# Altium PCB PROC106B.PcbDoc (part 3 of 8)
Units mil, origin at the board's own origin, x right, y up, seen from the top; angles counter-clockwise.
Board outline 4498.18 x 1060.53 mil, 8 copper layers (Top Layer, GND1, Sig1, PWR1, PWR2, Sig2, GND2, Bottom Layer), stack 69.602 mil thick; 439 components, 327 nets, 1548 pads, 843 vias.
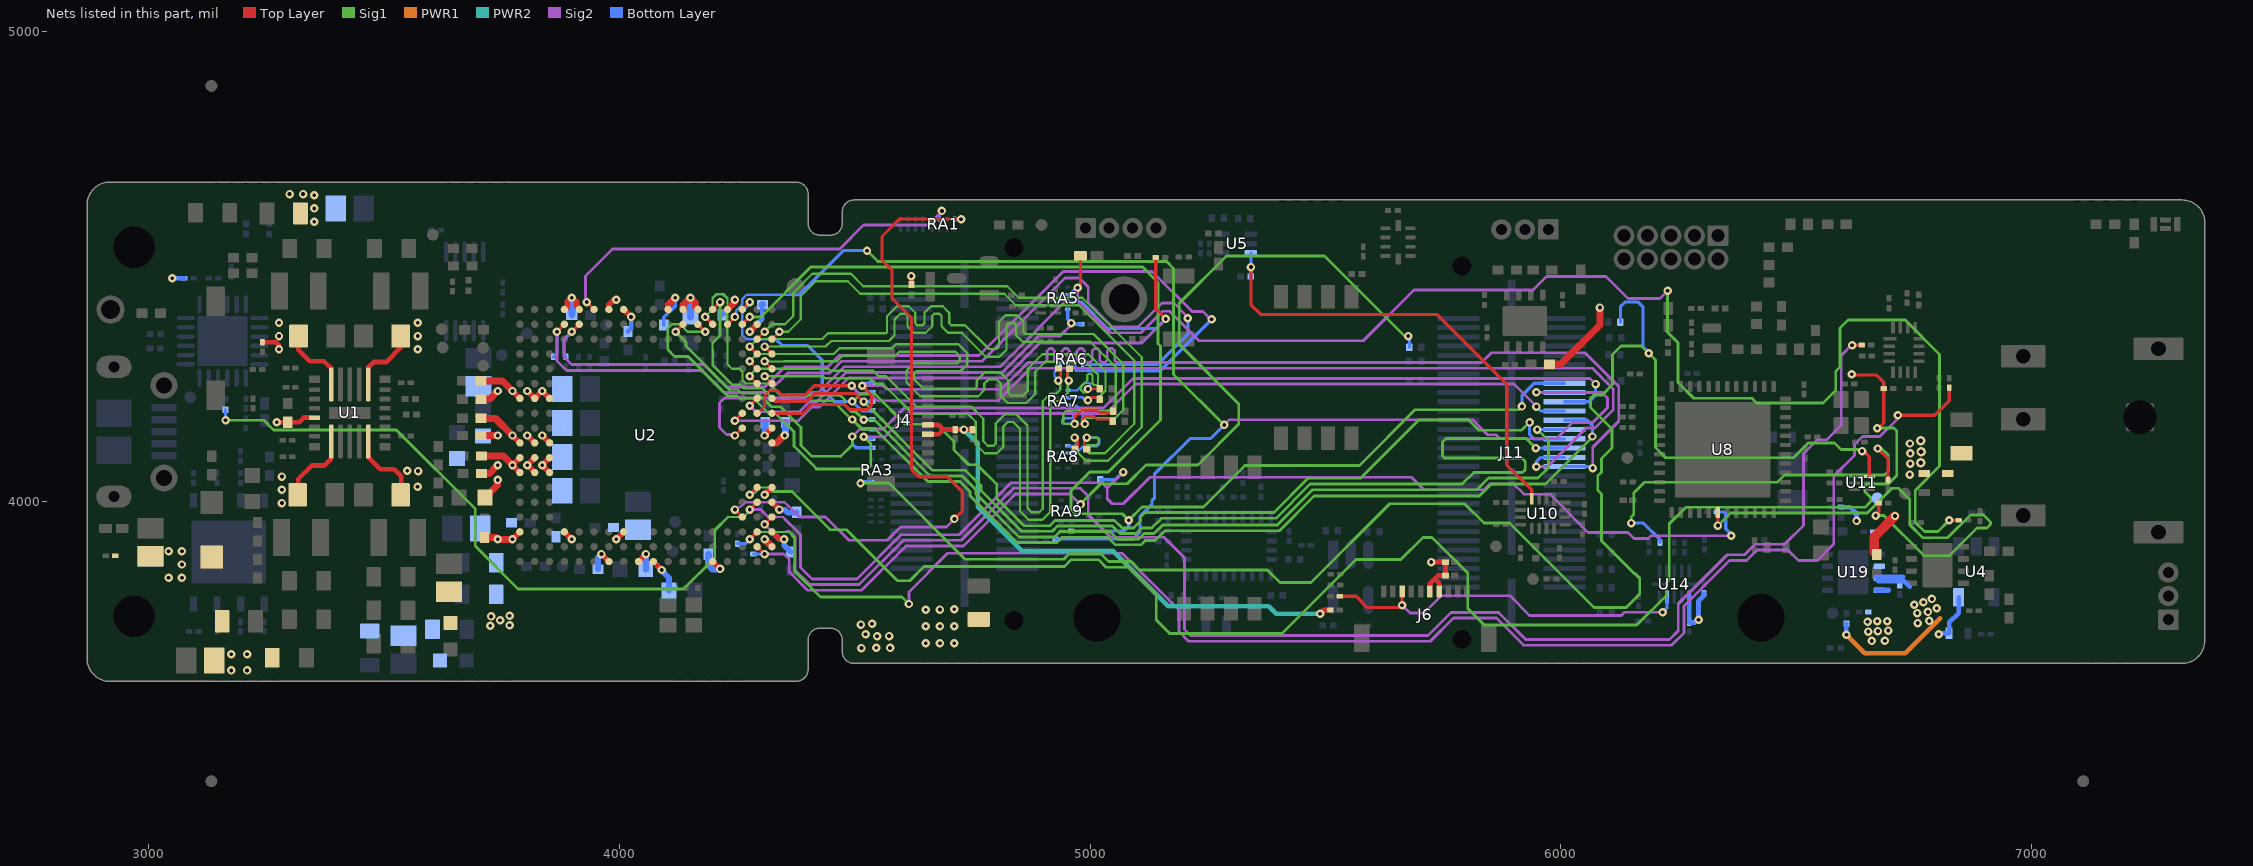
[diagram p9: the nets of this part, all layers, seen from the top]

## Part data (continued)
R52: library part CMP-0090496-1, "Res Thick Film 0201 1.96K Ohm 1% 1/20W 200ppm/C Molded SMD T/R", Digikey Part Number=P122807CT-ND, Manufacturer=Panasonic, Mouser Part Number=667-ERJ-1GNF1961C, Operating Temperature Range="-55°C to +125°C", Power_W=50mW, TempCo=200ppm/°C, Tolerance_%=1%
R53 R54 R55 R56: library part CMP-0026363-2, "RES, 3.83, 1%, 0.063 W, AEC-Q200 Grade 0, 0402", Manufacturer=Vishay-Dale, Power_W=63mW, Supplier Part Number 1=541-3.83LLCT-ND, TempCo="100 ppm/C", Tolerance_%=1%, Value2=0.063W, Value_Code=3R83, ValueDisplayed=3.83
R79 R180 R181: library part CMP-0087184-1, "RESISTOR, 0201, 0.05W, 1%, 4K7", Manufacturer="Panasonic Electronic Components", Power_W=50mW, TempCo=200ppm/°C, Tolerance_%=1%
R114 R117 R119 R126: library part CMP-0026491-2, "RES, 61.9, 1%, 0.063 W, AEC-Q200 Grade 0, 0402", Manufacturer=Vishay-Dale, Power_W=63mW, Supplier Part Number 1=541-61.9LCT-ND, TempCo="100 ppm/C", Tolerance_%=1%, Value2=0.063W, Value_Code=61R9, ValueDisplayed=61.9
R158 R170 R172: library part CMP-0090499-1, "Res Thick Film 0201 82.5K Ohm 1% 1/20W ±200ppm/°C Molded SMD SMD T/R", Digikey Part Number=P123175CT-ND, Manufacturer=Panasonic, Mouser Part Number=667-ERJ-1GNF8252C, Operating Temperature Range="-55°C to +125°C", Power_W=50mW, TempCo=200ppm/°C, Tolerance_%=1%
R159 R171: library part CMP-0090503-1, "Res Thick Film 0201 750 Ohm 5% 0.05W(1/20W) ±200ppm/C Pad SMD Automotive T/R", Digikey Part Number=P123367CT-ND, Manufacturer="Panasonic Electronic Components", Mouser Part Number=667-ERJ-1GNJ751C, Operating Temperature Range="-55°C to +125°C", Power_W=50mW, TempCo=200ppm/°C, Tolerance_%=5%
R174 R176: library part CMP-0090498-1, "Res Thick Film 0201 7.87K Ohm 1% 1/20W ±200ppm/°C Molded SMD SMD T/R", Digikey Part Number=P123160CT-ND, Manufacturer=Panasonic, Mouser Part Number=667-ERJ-1GNF7871C, Operating Temperature Range="-55°C to +125°C", Power_W=50mW, TempCo=200ppm/°C, Tolerance_%=1%
RA1 RA2 RA3 RA4 RA5 RA6 RA7 RA8 RA9: library part CMP-0087186-1, "RES ARRAY 4 RES ZERO OHM 0502", Manufacturer="Panasonic Electronic Components", Power_W=100mW, TempCo=-200/+600ppm/°C, Tolerance_%=5%
S1 S2: library part CMP-0002128-2, "Switch, Slide, SPST 4 poles, SMT", CurrentRating_mA=25A, Manufacturer="CTS Electrocomponents", Supplier Part Number 1=CT2184LPST-ND
S3: library part CMP-0087181-1, "SWITCH SLIDE DIP SPST 100MA 6V", Manufacturer="Nidec Copal Electronics"
SW2 SW3: library part CMP-0002150-2, "SWITCH TACTILE SPST-NO 0.05A 12V", CurrentRating_mA=50A, Manufacturer="Omron Electronic Components", Supplier Part Number 1=SW1020CT-ND
TP2 TP3 TP4 TP5 TP6 TP7 TP8 TP9 TP10 TP12 TP13 TP14 TP15 TP16 TP17 TP18 TP19 TP26 TP27 TP46: library part CMP-0078143-3, "TEST POINT.  No entry in BOM.", Manufacturer=N/A
TP11: library part CMP-0003825-1, "1mm Test Point, SMT", Manufacturer=Any
TP20: library part CMP-0086474-1, "PC Test Point, Loop Brass, Tin Plating 0.047\" (1.19mm) Hole Diameter Mounting Type", Manufacturer="Keystone Electronics"
U1: library part CMP-0079120-2, "4-A + 2.5-A + Two 1.5-A Buck Converters With Integrated Switches, RNF0026C (VQFN-HR-26)", Alternate Manufacturer="Texas Instruments", Alternate PartNumber=LP87524JRNFTQ1
U2: library part CMP-0090288-2, Manufacturer="Texas Instruments", Operating Temperature Range=to
U3: library part CMP-0087172-1, "I/O Controller Interface IC USB to Dual UART bridge", Manufacturer="Silicon Labs"
U4: library part CMP-0035419-1, "Single Output High PSRR LDO, 200 mA, Fixed 3 V Output, 2.7 to 5.5 V Input, 5-pin SOT-23 (DBV), -40 to 85 degC, Green (RoHS & no Sb/Br)", Manufacturer="Texas Instruments", Rating=Catalog
U5: library part CMP-0067398-2, "Automotive Grade, 1.4V-Capable +/-0.5degC Temperature Sensor with Alert Function and I2C/SMBus, DRL0006A (SOT-OTHER-6)", Alternate Manufacturer="Texas Instruments"
U6: library part CMP-0087170-1, "8KB I2C SER EEPROM TSOT 23", Manufacturer="ON Semiconductor"
U7: library part CMP-0087171-1, "IMU ACCEL/GYRO/MAG I2C 32BIT", Manufacturer="Hillcrest Laboratories, Inc."
U8: library part CMP-0083675-2, "SimpleLink(TM) Bluetooth(R) 5 low energy Wireless MCU, RGZ0048A (VQFN-48)", Alternate Manufacturer="Texas Instruments", Alternate PartNumber=CC2642R1FRGZT, Operating Temperature Range="-40 to 85 C", Rating=#N/A
U9: library part CMP-0079267-1, "2.3V-3.6V, 16M-BIT [x 1/x 2/x 4] CMOS FLASH Memory, WSON-8", Manufacturer="Macronix International Co., LTD", Supplier Part Number 1=1092-1211-ND
U10: library part CMP-0043349-1, "Low-Voltage 8-Bit I2C and SMBus I/O Expander, 1.65 to 5.5 V, -40 to 85 degC, 16-pin UQFN (RSV), Green (RoHS & no Sb/Br)", 5V Tolerant I/O=Yes, Manufacturer="Texas Instruments", Max Frequency(kHz)=400
U11: library part CMP-0050992-5, "1-Channel, 2:1 Analog Switch, DSF0006A (X2SON-6)", F @ Nom Voltage(Max)(Mhz)=150, Generic Part Number=SN74LVC1G3157, ICC @ Nom Voltage(Max)(mA)=0.01, Manufacturer="Texas Instruments", Operating Temperature Range="-40 to 85 C", Rating=Catalog, tpd @ Nom Voltage(Max)(ns)=2,1.2,0.8,0.3, Voltage(Nom)(V)=1.8,2.5,3.3,5
U12 U17: library part CMP-0065183-3, "Automotive Fault Protected CAN Transceiver With Flexible Data-Rate, DRB0008F (VSON-8)", Alternate Manufacturer="Texas Instruments", Alternate PartNumber=TCAN1042HGVDRBTQ1, Operating Temperature Range="-55 to 125 C", Rating=Automotive
U13: library part CMP-0067415-1, "10-Ohm Quad SPDT Analog Switch, RSV0016A (UQFN-16)", Alternate Manufacturer="Texas Instruments"
U14: library part CMP-0860038-1, "Automotive 4-Bit Bidirectional Voltage-Level Translator with Auto Direction Sensing and +/-15kV ESD, RUT0012A (UQFN-12)", Alternate Manufacturer="Texas Instruments", Operating Temperature Range="-40 to 125 C", Rating=Automotive
U15: library part CMP-0074545-1, "Dual 10-ohm SPDT Analog Switch, RSE0010A (UQFN-10)", Alternate Manufacturer="Texas Instruments"
U16: library part CMP-0087998-2, "AND Gate IC 1 Channel  6-SON (1x1)", Digikey Part Number=296-30121-1-ND, Manufacturer="Texas Instruments", Max Supply Voltage=5.5V, Min Supply Voltage=1.65V, Mouser Part Number=595-SN74LVC1G11DSFR, Operating Temperature Range="-40°C to +125°C"
U18: library part CMP-0074341-1, "Automotive Catalog Dual 15-Ohm SPDT Analog Switch, DGS0010A (VSSOP-10)", Alternate Manufacturer="Texas Instruments"
U19: library part CMP-0043358-3, "Dual In / Single Out Autoswitching Power Mux, 2.8 to 5.5 V, -40 to 85 degC, 8-pin SON (DRB), Green (RoHS & no Sb/Br)", IN1, IN2 Input Voltage(Max)(V)=5.5, IN1, IN2 Input Voltage(Min)(V)=2.8, IN1 Output Current(Max)(A)=1.25, Manufacturer="Texas Instruments"
Y1: library part CMP-0090505-1, "40MHz ±10ppm Crystal 8pF 50 Ohms 4-SMD, No Lead", Digikey Part Number=FW4000044QDICT-ND, Frequency_Fixed=40MHz, Frequency Stability=50ppm, Frequency Tolerance=10ppm, Load Capacitance=8pF, Manufacturer=Diodes, Mouser Part Number=729-FW4000044Q, Operating Temperature Range="-40°C to +125°C"
Y2: library part CMP-0088076-1, "48MHz ±20ppm Crystal 7pF 50 Ohms 4-SMD, No Lead", Frequency_Fixed=48MHz, Frequency Tolerance=20ppm, Load Capacitance=7pF, Manufacturer=Kyocera
Y3 Y4: library part CMP-0088006-1, "CRYSTAL 32.768KHZ 4PF SMD", Frequency_Fixed=32.768kHz, Frequency Tolerance=20ppm, Load Capacitance=4pF, Manufacturer="Abracon LLC"
ZZ1: library part CMP-0003616-3
ZZ2: library part CMP-0077236-1
ZZ3: library part CMP-0077237-1
ZZ4 ZZ5.2: library part CMP-0077238-1
ZZ5.1: library part CMP-0077238-1, "Cut the thermal pad(Part Number#GPVOUS-0.125-AC-0816) for the shape and size of the inner surface of the heatsink(Part Number#160018120021) and paste it on the inner surface of the heatsink;"

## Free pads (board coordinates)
  round 19 hole 24 unplated: ""(3145.41,4687.43) ""(3145.41,3610.9) ""(3175.41,4687.43) ""(3175.41,3610.9) ""(3205.41,4687.43) ""(3205.41,3610.9) ""(3235.41,4687.43) ""(3235.41,3610.9) ""(3265.41,4687.43) ""(3265.41,3610.9) ""(3637.19,4687.43) ""(3637.19,3610.9) ""(3667.19,4687.43) ""(3667.19,3610.9) ""(3697.19,4687.43) ""(3697.19,3610.9) ""(3727.19,4687.43) ""(3727.19,3610.9) ""(3757.19,4687.43) ""(3757.19,3610.9) ""(4128.97,3610.9) ""(4128.97,4687.43) ""(4158.97,3610.9) ""(4158.97,4687.43) ""(4188.97,4687.43) ""(4188.97,3610.9) ""(4218.97,3610.9) ""(4218.97,4687.43) ""(4248.97,3610.9) ""(4248.97,4687.43) ""(4646.5,3648.05) ""(4676.5,3648.05) ""(4706.5,3648.05) ""(4736.5,3648.05) ""(4766.5,3648.05) ""(5409.11,4649.48) ""(5439.11,4649.48) ""(5469.11,4649.48) ""(5499.11,4649.48) ""(5529.11,4649.48) ""(5950.52,3648.05) ""(5980.52,3648.05) ""(6010.52,3648.05) ""(6040.52,3648.05) ""(6070.52,3648.05) ""(7097.6,3648.05) ""(7097.68,4649.43) ""(7127.6,3648.05) ""(7127.68,4649.43) ""(7157.6,3648.05) ""(7157.68,4649.43) ""(7187.6,3648.05) ""(7187.68,4649.43) ""(7217.6,3648.05) ""(7217.68,4649.43)

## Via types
v1: diameter 18, hole 8, Top Layer to Bottom Layer, tented both sides, 804 vias
v2: diameter 19.68, hole 7.87, Top Layer to Bottom Layer, tented both sides, 34 vias
v3: diameter 20, hole 10, Top Layer to Bottom Layer, tented both sides, 3 vias
v4: diameter 18, hole 8, Top Layer to Bottom Layer, 1 vias
v5: diameter 17, hole 7.87, Top Layer to Bottom Layer, 1 vias

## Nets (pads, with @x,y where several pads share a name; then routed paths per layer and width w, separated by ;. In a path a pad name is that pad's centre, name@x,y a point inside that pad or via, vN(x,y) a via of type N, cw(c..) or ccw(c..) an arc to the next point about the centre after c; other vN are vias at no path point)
3V0: C7.1 C15.1 C16.1 C115.1 C116.1 C118.1 J4.6 J4.7 J6.6 J6.7 R79.2 R181.2 U4.5 U14.1 | length 1553.4
  Top Layer w10: J4.7@4655.33,4143.81 4678.32,4143.81 4688.3,4153.79 ; J4.6@4655.33,4163.49 4678.59,4163.49 4688.3,4153.79 ; C15.1@4750.21,4153.69 4750.12,4153.79 v1(4731.8,4153.79) C16.1@4713.47,4153.79 4688.3,4153.79 ; v1(5488.42,3762.4) 5496.67,3770.65 R181.2@5510.03,3770.65 ; J6.6@5721.75,3810.06 5721.75,3826.54 5731.98,3836.77 ; v1@5724.8,3872.26 5724.87,3872.2 C115.1@5754.85,3872.2 C116.1@5754.85,3843.74 5738.95,3843.74 5731.98,3836.77 ; J6.7@5741.43,3807.06 5741.43,3827.32 5731.98,3836.77
  PWR2 w10: v1(4731.8,4153.79) 4761,4124.58 4761,3989.4 4854.25,3896.15 5048.17,3896.15 5165.74,3778.57 5379.01,3778.57 5395.18,3762.4 v1(5488.42,3762.4)
  Bottom Layer w10: U14.1@6272.54,3799.77 6272.54,3764.35 6272.5,3764.32 C118.1@6272.5,3743.88 6284.34,3743.88 6292.44,3751.98 6292.44,3789.79 6304.11,3801.46 R79.2@6304.11,3805.64 ; v1(6802.79,3718.79) 6804.79,3720.79 C7.1@6824.78,3720.79 6824.78,3743.97 6844.78,3763.97 U4.5@6844.78,3797.49
  other v1: 6292.44,3749.79 5724.6,3872.26
5V_HD_IN: C128.1 L16.2 R20.1 U19.8 | length 78.8
  Bottom Layer w10: R20.1@6594.7,3988.94 6614.05,3988.94 6628.05,3974.95 v1(6628.05,3959.58)
  Bottom Layer w12: U19.8@6671.07,3812.08 6695.37,3812.08
  other v1: 4650.94,3699.61 4681.04,3699.61 4711.61,3699.61 6660.22,3704.68 6688.14,3705.36 6652.66,3724.54 6673.29,3725.69 6695.37,3726.86 4650.94,3735.76 4681.04,3735.76 4711.61,3735.76 6651.3,3745.4 6671.76,3746.63 6693.22,3746.68 4650.93,3770.89 4681.04,3771.4 4711.61,3772.13
5V_IN: C1.2 C4.1 C30.1 C50.1 C51.1 C52.1 C53.1 C129.1 D1.1 FL3.2 FL12.2 R27.1 R39.1 R50.2 R64.1 R107.1 U1.9 U1.13 U1.18 U1.22 U1.26 U19.7 | length 1553.7
  Top Layer w10: R50.2@3241.63,4339.44 3270.32,4339.44 3277.02,4332.74 v1@3277.02,4326.81 ; v1(3272.33,4169.32) C30.1@3295.87,4169.32 3319.81,4169.32 3329.65,4179.16 U1.18@3352.68,4179.16 ; C50.1@3318.11,4009.52 3318.11,4048.7 3346.62,4077.21 3373.07,4077.21 3388.04,4092.18 ; C52.1@3318.11,4368.48 3318.11,4323.58 3342.64,4299.04 3372.63,4299.04 3388.11,4283.56 U1.13@3388.11,4249.63 ; 3388.11,4092.18 U1.22@3388.11,4128.37 ; U1.26@3466.85,4128.37 3466.85,4094.45 3492.01,4069.29 3521.99,4069.29 3536.85,4054.43 C51.1@3536.85,4009.52 ; U1.9@3466.85,4249.63 3466.85,4285.9 3478.07,4297.12 3504.66,4297.12 3536.85,4329.31 C53.1@3536.85,4368.48 ; v1(4620.27,4479.75) 4620.57,4479.46 R107.1@4620.57,4461.7
  Top Layer w15: FL12.2@5975.6,4292.41 5999,4292.41 6082.75,4376.16 v1(6082.75,4412.79)
  Top Layer w20: FL3.2@6670.79,3888.25 6665.81,3893.23 6665.81,3926.17 v5(6709.55,3969.91)
  PWR1 w10: v1(6606.39,3717.68) 6645.55,3678.52 6731.31,3678.52 6805.46,3752.67
  Bottom Layer w10: v1(3050.47,4475.15) R64.1@3076.13,4475.15 ; v1(6606.39,3717.68) R27.1@6606.39,3741.52 ; U19.7@6673.76,3836.69 6698.11,3836.69 6703.21,3831.6 ; 6711.81,3839.4 6710.11,3841.1 ; 6726.91,3841.1 6710.11,3841.1 ; 6740.73,3819.94 6729.08,3831.6 6703.21,3831.6 ; 6703.21,3831.6 6673.82,3831.6 6669.11,3840.2 6670.01,3841.1 6710.11,3841.1
  other v1: 4514.3,3689.55 4545.9,3690.22 4574.96,3689.89 4547.43,3714.8 4572.89,3715.13 4522.96,3718.74 4513.24,3739.55 4536.9,3741.13 6757.93,3742.77 6782.31,3747.33 6756.77,3763.83 6779.56,3766.42 6798.43,3774.05 6750.69,3781.76 6770.14,3787.01 6788.19,3794.02 3042.55,3838.89 3070.75,3838.89 3070.75,3867.09 3042.55,3895.28 3070.75,3895.28 3283.23,3997.47 3283.23,4025.66 3571.45,4032.48 3283.23,4053.86 3549.23,4066.35 3572.38,4065.53 3277.02,4324.15 3571.73,4324.15 3277.02,4352.35 3571.73,4352.35 3277.02,4380.54 3571.73,4380.54
5V_IN_B: C42.2 C122.1 C127.1 L15.2 TP4.1 U19.6
  other v1: 6741.2,4058 6741.81,4081.54 6741.81,4103 6741.32,4124.11
  other v3: 6764.6,4082.97 6765.01,4106.67 6764.46,4130
ALERT: R38.1 U5.3 U10.4 | length 1009.2
  Top Layer w6.7: v1(5341.5,4498.97) 5341.5,4418.98 5362.14,4398.33 5736.3,4398.33 5885.05,4249.58 5885.05,4078.41 5937.93,4025.53 U10.4@5937.93,4006.69
  Bottom Layer w6.7: R38.1@5341.5,4478.82 v1(5341.5,4498.97) U5.3@5341.5,4529.03 U5.3@5341.84,4528.69
AR_1P0_RF1: C75.2 C78.1 C79.1 C80.1 C81.1 C113.1 C124.2 L12.2 U2.J16 U2.J17 U2.J18 | length 184.7
  Top Layer w12: v1(3773.02,4141.13) U2.J18@3788.76,4125.38 ; v1(3804.51,4141.13) U2.J17@3820.26,4125.38 ; v1(3836.01,4141.13) U2.J16@3851.76,4125.38
  Top Layer w15: C80.1@3705.88,4141.13 v1(3741.52,4141.13) ; C81.1@3705.88,4177.66 3736.48,4177.66 v1(3773.02,4141.13)
  other v1: 3725.88,3737.02 3766.78,3737.9 3746.66,3748.61 3727.42,3756.7 3766.78,3758.45
AR_1P0_RF2: C70.1 C74.1 C82.1 C83.1 C84.1 C85.1 C111.2 C121.1 C131.2 L14.2 U2.G16 U2.G17 U2.G18 U2.H16 U2.H17 U2.H18 | length 297.2
  Top Layer w12: U2.G18@3788.76,4062.39 v1(3773.02,4078.14) U2.H18@3788.76,4093.88 ; U2.G17@3820.26,4062.39 v1(3804.51,4078.14) U2.H17@3820.26,4093.88 ; U2.G16@3851.76,4062.39 v1(3836.01,4078.14) U2.H16@3851.76,4093.88
  Top Layer w15: C84.1@3707.42,4060.46 3723.84,4060.46 v1(3741.52,4078.14) ; C85.1@3707.42,4097.51 3753.64,4097.51 v1(3773.02,4078.14) ; C74.1@3714.74,4009.15 3741.52,4035.93 v1(3741.52,4046.64)
AR_1P2: C76.1 C91.2 C92.2 C94.1 C95.1 C96.1 C97.1 C98.1 C103.1 L13.2 U2.A5 U2.C1 U2.E1 U2.J1 U2.V4 U2.V6 U2.V7 U2.V8 U2.V12 U2.V14 U2.V15 | length 667.8
  Top Layer w12: U2.V15@3883.25,4408.84 3890,4415.59 3890,4425.59 3899,4434.59 3909,4424.59 3909,4417 3914.75,4411.25 U2.V14@3914.75,4408.84 ; U2.V12@3977.74,4408.84 3977.74,4418.84 3988.49,4429.59 v1(3993.49,4429.59) ; U2.A5@4198.21,3873.41 v1(4213.96,3857.66) ; U2.C1@4324.2,3936.4 4339.94,3920.65 v1(4349.94,3920.65) ; U2.E1@4324.2,3999.4 4324.33,3999.4 v1(4340.08,3983.65)
  Top Layer w15: U2.V8@4103.72,4408.84 4103.72,4418.45 v1(4118.96,4433.68) ; U2.V7@4135.22,4408.84 4135.22,4417.93 v1(4150.97,4433.68) 4161.76,4422.88 4161.76,4413.8 U2.V6@4166.72,4408.84 ; U2.V4@4229.71,4408.84 4245.46,4424.59 v1(4245.46,4429.68) ; U2.J1@4324.2,4125.38 4334.2,4125.38 v1@4350.05,4141.24
  Bottom Layer w8: C96.1@4094.31,4375.82 4094.31,4392.25 4118.96,4416.91 v1(4118.96,4433.68)
  Bottom Layer w10: v1@3898.96,4434.55 v1@3899,4434.59 ; v1(4150.97,4433.68) v1@4150.97,4434.59
  Bottom Layer w12: C91.2@4218.02,4397.33 4245.46,4424.77 v1(4245.46,4429.68) ; v1(4340.08,3983.65) 4351.45,3983.65 4358.24,3976.86 4375.3,3976.86 C95.1@4376.53,3978.09 ; v1@4350,3920 4350,3908 C94.1@4364,3894
  Bottom Layer w15: C98.1@3898.96,4396.76 v1@3898.96,4434.55 ; C103.1@4150.97,4392.63 v1(4150.97,4433.68) ; C97.1@4188.97,3888.79 4189.39,3888.36 4189.39,3866.45 4198.18,3857.66 v1(4213.96,3857.66) ; v1@4350.05,4141.24 4352.69,4143.87 C92.2@4352.69,4168.77
  other v1: 4351.25,4141.24 3899,4433.68 3352.15,4595.26 3352.15,4623.45 3352.15,4651.65 3299.59,4653.99 3328.09,4653.99
AR_1V4_APLL: C90.1 U2.A10 | length 56.1
  Top Layer w12: U2.A10@4040.73,3873.41 v1(4056.48,3889.16)
  Bottom Layer w10: C90.1@4056.23,3855.43 C90.1@4056.48,3855.68
  Bottom Layer w12: C90.1@4056.48,3855.68 v1(4056.48,3889.16)
AR_1V4_SYNTH: C89.1 U2.A9 | length 72
  Top Layer w12: U2.A9@4072.23,3873.41 v1@4087.98,3857.66
  Bottom Layer w12: v1(4090.2,3855.43) 4090.2,3853.81 4105.41,3838.6 C89.1@4105.41,3811.96
AR_1V8: C55.1 C56.1 C57.1 C58.1 C59.1 C60.1 C61.1 C62.1 C63.1 C64.1 C65.1 C66.1 C67.1 C68.1 C73.2 C112.1 L11.2 U2.A12 U2.B1 U2.C11 U2.C15 U2.C18 U2.F1 U2.K1 U2.M16 U2.M17 U2.M18 U2.U2 U2.V11 | length 635.6
  Top Layer w12: v1(3773.02,3920.65) U2.C18@3788.76,3936.4 ; v1(3773.02,4235.62) U2.M18@3788.76,4219.87 ; v1(3804.51,4235.62) U2.M17@3820.26,4219.87 v1(3836.01,4235.62) U2.M16@3851.76,4219.87 ; U2.C15@3883.25,3936.4 v1(3899,3920.65) ; v1(3961.99,3889.16) U2.A12@3977.74,3873.41 ; v1(3993.49,3920.66) U2.C11@4009.24,3936.4 ; U2.V11@4009.24,4408.84 v1(4024.98,4393.1) ; v1(4276.95,4361.6) U2.U2@4292.7,4377.35 ; v1(4308.45,4015.14) U2.F1@4324.2,4030.89 ; v1(4308.45,4141.13) U2.K1@4324.2,4156.88
  Top Layer w15: C58.1@3705.86,4218.19 3724.1,4218.19 v1(3741.52,4235.62) ; C57.1@3705.86,4257.19 3751.44,4257.19 v1(3773.02,4235.62) ; C68.1@3713.57,3924.11 3738.07,3924.11 v1(3741.52,3920.65) v1(3773.02,3920.65) ; v1(4308.45,3920.65) U2.B1@4324.2,3904.91
  Bottom Layer w10: C61.1@4018.33,4361.9 4024.98,4368.55 v1(4024.98,4393.1) ; v1(4276.95,4361.6) 4303.38,4388.02 C56.1@4303.38,4418.18 ; v1(4308.45,4141.13) v1@4309.75,4142.43
  Bottom Layer w12: C63.1@3954.76,3856.83 3954.76,3881.92 v1(3961.99,3889.16)
  Bottom Layer w15: C56.1@4303.38,4418.18 C56.1@4304.26,4419.07 ; v1@4309.75,4142.43 C60.1@4309.75,4168.77
  other v1: 3175.57,3642.06 3209.12,3642.06 3175.57,3676.64 3209.12,3676.64
AR_BSS_LOGGER: RA1.4 U2.D3 | length 1457.8
  Top Layer w6.7: v1(4245.46,3983.65) U2.D3@4261.2,3967.9 ; v1(4711.71,3963.9) 4728.31,3980.49 4728.31,4021.77 4696.67,4053.41 4635.8,4053.41 4620.6,4068.61 4620.6,4390.98 4579.49,4432.09 4579.49,4491.76 4557.8,4513.46 4557.8,4563.91 4594.61,4600.72 4725.6,4600.72 v1(4725.75,4600.58)
  Sig2 w4.5: v1(4245.46,3983.65) 4250.76,3988.95 4256.7,3988.95 4267.15,3999.4 4350.75,3999.4 4358.91,3991.23
  Sig2 w5.95: 4358.91,3991.23 4382.26,3967.89 4438.09,3967.89 4487.48,3918.5 4569.04,3918.5 4597.24,3946.7 4694.51,3946.7 v1(4711.71,3963.9)
  Bottom Layer w6.7: RA1.4@4711.71,4600.58 v1(4725.75,4600.58)
AR_CS1: R9.2 R139.2 U2.C2 | length 3317
  Top Layer w6.7: v1(4276.95,3920.66) U2.C2@4292.7,3936.4 ; v1(6715.81,4184) 6794.11,4184 6824.81,4214.7 R139.2@6824.81,4242.98
  Sig1 w4.5: v1(4276.95,3920.66) 4292.55,3936.25 ; 4292.57,3936.4 4359.48,3936.4 4367.2,3928.68
  Sig1 w5.95: 4367.2,3928.68 4372.68,3923.2 4372.68,3852.89 4427.56,3798 4600.39,3798 v1(4615.19,3783.2)
  Sig2 w5.95: v1(4615.19,3783.2) 4615.19,3808.93 4697.19,3890.93 5068.04,3890.93 5188.57,3770.4 5188.57,3724.39 5208.81,3704.15 5722.57,3704.15 5771.73,3753.31 5862.89,3753.31 5920.43,3695.78 6235.45,3695.78 6261.24,3721.57 6261.24,3778.92 6358.17,3875.85 6394.55,3875.85 6416.88,3898.18 6481.96,3898.18 6504.38,3875.76 6544.85,3875.76 6579.54,3910.44 6579.54,4054.9 6623.31,4098.68 6623.31,4121.75 6640.56,4138.99 6677.31,4138.99 6715.81,4177.5 v1(6715.81,4184)
  Bottom Layer w6.7: R9.2@4250.53,3911.55 4267.85,3911.55 v1(4276.95,3920.66)
AR_CS1_60PIN: R150.2 RA3.1 U11.3 | length 3577.1
  Top Layer w6.7: v1@6639.79,4111.11 6655.07,4095.82 U11.3@6655.07,4054.07
  Sig1 w5.95: v1(4512.23,4039.9) 4572.79,4039.9 4734.57,3878.13 4943.97,3878.13 4955.07,3889.24 5022.69,3889.24 5038.76,3873.16 5087.38,3873.16 5105.13,3855.41 5376.27,3855.41 5403.06,3828.62 5468.8,3828.62 5636.32,3996.14 5795.11,3996.14 5836.32,3954.93 5891.16,3954.93 6070.18,3775.91 6138.83,3775.91 6167.52,3804.59 6167.52,3837.84 6157.87,3847.49 6156.34,3847.49 6086.26,3917.56 6086.26,4017.07 6078.05,4025.28 6078.05,4054.78 6086.26,4062.99 6086.26,4092.5 6108.35,4114.59 6108.35,4155.16 6062.88,4200.64 6062.88,4220.16 6069.96,4227.25 6087.72,4227.25 6109.66,4249.18 6109.66,4313.09 6127.8,4331.24 6171.18,4331.24 v1(6186.75,4315.67) 6200.65,4301.78 6200.65,4115.91 6222.76,4093.79 6494.18,4093.79 6525.34,4124.95 6581.02,4124.95 6594.86,4111.11 v1@6639.79,4111.11
  Bottom Layer w6.7: v1(4512.23,4039.9) 4513.87,4039.9 4517.57,4043.61 RA3.1@4535.95,4043.61 ; R150.2@6126.41,4381.76 6126.41,4414.59 6136.18,4424.36 6164.48,4424.36 6174.21,4414.64 6174.21,4330.28 6186.75,4317.73 v1(6186.75,4315.67)
  other v1: 6639.79,4107.91
AR_CS1_BT: R105.2 U8.30 | length 1081.1
  Top Layer w6.7: v1(6333.54,3949.8) U8.30@6333.54,3977.25 ; v1(6668.81,3971.01) 6675.01,3977.22 R105.2@6675.01,3997.34
  Sig1 w5.95: v1(6333.54,3949.8) 6360.37,3976.64 6650.73,3976.64 6703.16,4029.07 6717.11,4029.07 6740.89,4005.29 6740.89,3951.61 6768.42,3924.08 6821.79,3924.08 6869.97,3972.26 6897.81,3972.26 6912.48,3957.59 6912.48,3951.77 6905.1,3944.39 6884.07,3944.39 6825.56,3885.88 6770.99,3885.88 6685.86,3971.01 v1(6668.81,3971.01)
AR_CS1_LCD: R76.2 R106.2 | length 847.6
  Top Layer w6.7: v1(6673.04,4113.48) 6673.04,4113.33 6695.04,4091.34 R106.2@6695.04,4046.53
  Sig1 w5.95: v4(6149.58,3955.16) 6149.58,3967.73 6154.54,3972.7 6154.54,4018.54 6178,4042 6459.94,4042 6475.03,4057.09 6687.59,4057.09 6695.45,4064.95 6695.45,4099.24 6681.21,4113.48 v1(6673.04,4113.48)
  Bottom Layer w6.7: v4@6150.63,3956.21 v4(6149.58,3955.16) 6174.89,3955.16 6210.78,3919.27 R76.2@6210.78,3913.46
AR_CS1_LCD_T: J6.3 R183.1 U14.4 | length 808.1
  Top Layer w6.7: R183.1@5530.62,3799.62 5564.89,3799.62 5589,3775.51 5662.69,3775.51 v1(5662.69,3780.5) J6.3@5662.69,3810.06
  Sig2 w5.95: v1(5662.69,3780.5) 5679.39,3763.8 5708.98,3763.8 5746.07,3800.89 5891.53,3800.89 5933.37,3759.05 6128.25,3759.05 6135,3765.81 v1(6215.84,3765.81)
  Bottom Layer w6.7: v1(6215.84,3765.81) 6225.29,3775.26 U14.4@6225.29,3797.8
AR_DMM_CLK: J11.15 R11.1 U2.U3 | length 2863.5
  Top Layer w6.7: U2.U3@4261.2,4377.35 v1(4276.95,4393.1)
  Sig1 w5.95: v1(4276.95,4393.1) 4300.77,4393.1 4406.49,4498.81 5111.66,4498.81 5144.37,4466.1 5144.37,4336.15 5149.25,4331.27 5149.25,4174.31 5038.48,4063.54 4999.25,4063.54 4959.53,4023.82 4959.53,3983.93 4968.69,3974.76 5068.35,3974.76 v1(5082.11,3961) 5110.48,3989.37 5240.5,3989.37 5328.59,4077.46 5572.06,4077.46 5690.34,4195.73 5910.11,4195.73 v1(5917.11,4202.74)
  Bottom Layer w6.7: R11.1@4960.02,3937.94 5071.27,3937.94 5082.11,3948.78 v1(5082.11,3961) ; v1(5917.11,4202.74) 5917.11,4225.75 5943.5,4252.14 J11.15@6007.91,4252.14
AR_DMM_SYNC: J11.17 R10.1 U2.U4 | length 3035.4
  Top Layer w6.7: U2.U4@4229.71,4377.35 v1(4245.46,4393.1)
  Sig1 w5.95: v1(4526.01,4533.75) 4549.05,4510.71 5162.64,4510.71 5177.31,4496.03 5177.31,4270.93 v1(5284.75,4163.49)
  Sig2 w5.95: v1(5284.75,4163.49) 5296,4174.75 5811.84,4174.75 5843.88,4142.71 5862.4,4142.71 5871.08,4134.03 5990.13,4134.03 6024.74,4168.63 6067.55,4168.63 6099.07,4200.15 6099.07,4221.06 6087.61,4232.53 5948.46,4232.53 v1(5947.91,4233.07)
  Bottom Layer w5: v1(4245.46,4393.1) 4247.94,4395.58 4247.94,4406.09 4261.2,4419.35 4261.2,4430.66 4261.25,4430.71 4261.25,4431.1 4270.45,4440.29 4287.98,4440.29 4382.34,4440.31 4385,4442.97
  Bottom Layer w5.5: J11.17@6007.91,4232.45 J11.17@6008.02,4232.56
  Bottom Layer w6.7: 4385,4442.97 4475.78,4533.75 v1(4526.01,4533.75) ; R10.1@4927.02,3921 5090.97,3921 5106.23,3936.25 5106.23,3969.32 5131.09,3994.18 5131.09,4002.21 5136.5,4007.62 5136.5,4058.65 5212.51,4134.66 5255.92,4134.66 v1(5284.75,4163.49) ; v1@5946.67,4229.5 v1@5947.91,4230.74 ; v1(5947.91,4233.07) v1@5947.91,4230.74 ; J11.17@6007.91,4232.45 5949.62,4232.45 v1@5947.91,4230.74
AR_DP0: J11.19 R88.1 U2.U7 | length 2348.9
  Top Layer w6.7: v1(4119.47,4361.6) U2.U7@4135.22,4377.35
  Sig1 w4.5: 4233.93,4238.41 4252.3,4238.41 4260.24,4230.47 4294.69,4230.47
  Sig1 w5.95: v1(4119.47,4361.6) 4141.45,4339.62 4141.45,4330.89 4233.93,4238.41 ; 4295.71,4229.45 4323.07,4202.09 4342.27,4202.09 4385.89,4158.47 4385.89,4120.26 4409.3,4096.84 4469.39,4096.84 4469.78,4096.45 4494.9,4121.58 v1(4494.9,4138.98)
  Sig2 w5.95: v1(4494.9,4138.98) 4511.03,4155.1 4560.94,4155.1 4605.25,4199.42 5028.67,4199.42 5091.43,4262.18 6061.63,4262.18 v1(6073.52,4250.28)
  Bottom Layer w6.7: v1@4494.9,4134.98 4494.9,4123.11 4503.04,4114.97 R88.1@4537.25,4114.97 ; J11.19@6007.91,4212.77 6060.26,4212.77 6073.52,4226.03 v1(6073.52,4250.28)
AR_DP1: J11.21 R130.1 U2.U6 | length 2360.1
  Top Layer w6.7: U2.U6@4166.72,4377.35 v1(4182.46,4361.6)
  Sig1 w4.5: 4103,4368.42 4111.93,4377.35 4128.99,4377.35 4144.74,4361.6 v1(4182.46,4361.6) ; 4229.91,4225.61 4250.33,4225.61 4255.92,4220.03 4284.86,4220.03 4316.74,4188.14
  Sig1 w5.95: 4103,4368.42 4103,4323.28 4117.2,4309.08 4146.44,4309.08 4229.91,4225.61 ; 4316.74,4188.14 4331.88,4188.14 4370.86,4149.16 4370.86,4118.46 4417.54,4071.79 4417.54,4069.92 4526.78,4069.92 4534.17,4077.3 4534.17,4123.47 v1(4519,4138.63)
  Sig2 w5.95: v1(4519,4138.63) 4564,4138.63 4612.89,4187.52 5033.59,4187.52 5096.35,4250.28 5900.26,4250.28 v1(5947.9,4202.64)
  Bottom Layer w6.7: v1@4519,4134.63 R130.1@4537.25,4134.63 ; v1(5947.9,4202.64) 5957.46,4193.08 J11.21@6007.91,4193.08
AR_DP2: J11.23 R132.1 U2.V5 | length 2435.9
  Top Layer w5.5: v1(4213.96,4424.59) v1@4214.41,4425.04
  Top Layer w6.7: U2.V5@4198.21,4408.84 v1(4213.96,4424.59)
  Sig1 w4.5: 4198.21,4322.56 4198.21,4336.63 4198.21,4337.65 ; 4240.31,4248.86 4256.63,4248.86 4264.57,4240.92 4304.42,4240.92
  Sig1 w5.95: 4198.21,4322.56 4198.21,4290.95 4239.58,4249.58 ; 4198.21,4337.65 4213.96,4353.4 v1(4213.96,4424.59) ; 4305.18,4240.16 4330.57,4214.77 4453.46,4214.77 4488.56,4179.67 4490.32,4179.67 v1(4494.9,4175.09) 4514.89,4155.1 4543.36,4155.1 4655.16,4043.31 4723.42,4043.31 4745.07,4021.66 4745.07,4013.15 4844.29,3913.93 4929.3,3913.93 4940.54,3925.16 5037.22,3925.16 5053.54,3908.85 5107.85,3908.85 5117.16,3918.16 5137.98,3918.16 5158.66,3938.83 5402.06,3938.83 5475.84,4012.61 5826.59,4012.61 5852.07,4038.09 5966.94,4038.09 6066.87,4138.03 v1(6066.87,4138.99)
  Bottom Layer w6.7: v1(4494.9,4175.09) 4514.56,4155.43 R132.1@4537.25,4155.43 ; J11.23@6007.91,4173.4 6056.48,4173.4 6066.87,4163.01 v1(6066.87,4138.99)
AR_DP3: J11.25 R133.1 U2.U5 | length 2407.4
  Top Layer w6.7: v1(4182.46,4393.1) U2.U5@4198.21,4377.35
  Sig1 w4.5: v1(4182.46,4393.1) 4198.21,4408.84 4198.21,4433.25 ; 4228.98,4361.6 4229.71,4360.88 4229.71,4292.08 4238.93,4282.86 4255.66,4282.86 4255.66,4282.75 4261.2,4277.2 4261.2,4259.06 4268.9,4251.36 4318.19,4251.36 ; 4228.98,4431.84 4228.98,4432.86 ; 4229.71,4411.06 4229.71,4433.15
  Sig1 w5.95: 4198.21,4433.25 4206.03,4441.06 4220.78,4441.06 4228.98,4432.86 ; 4228.98,4361.6 4228.98,4411.06 ; 4318.19,4251.36 4342.89,4226.67 4469.05,4226.67 4478.43,4217.29 4478.43,4206.63 4493.49,4191.56 4502.18,4191.56 v1(4519,4174.75) 4540.54,4174.75 4660.08,4055.2 4728.34,4055.2 4756.96,4026.58 4756.96,4018.07 4849.21,3925.82 4924.38,3925.82 4935.61,3937.06 5042.15,3937.06 5058.47,3920.74 5102.48,3920.74 5114.37,3932.63 5135.64,3932.63 5154.16,3951.16 5397.56,3951.16 5472.3,4025.89 5821.67,4025.89 5846.41,4050.63 5951.35,4050.63 5973.44,4072.73 5973.44,4130.25 v1(5949.98,4153.71)
  Bottom Layer w6.7: v1(4519,4174.75) R133.1@4537.25,4174.75 ; v1(5949.98,4153.71) J11.25@6007.91,4153.71
AR_DP4: J11.27 R135.1 U2.V3 | length 2293.3
  Top Layer w6.7: U2.V3@4261.2,4408.84 v1(4276.95,4424.59)
  Sig1 w5.95: v1(4494.9,4213.45) 4496.05,4213.45 4512.18,4229.58 4542.79,4229.58 4607.41,4164.95 4674.82,4164.95 4711.09,4128.67 4711.09,4110.12 4742.23,4078.99 4759.45,4078.99 4801.8,4036.65 4801.8,4006.88 4859.07,3949.61 4914.52,3949.61 4925.76,3960.85 5052,3960.85 5068.32,3944.53 5092.48,3944.53 5106.35,3958.4 5106.35,3967.82 5116,3977.47 5390.24,3977.47 5463.1,4050.33 5574.33,4050.33 5698,4174 5804,4174 5825.87,4152.13 5916.56,4152.13 v1(5933.38,4168.95)
  Bottom Layer w5: v1@4276.95,4419.75 4261.2,4404.01 4261.2,4355.5 4261.2,4355.08 4270.43,4345.85 4316.17,4345.85
  Bottom Layer w6.7: 4316.17,4345.85 4332.22,4345.85 4345.89,4332.18 4399.87,4332.18 4430.97,4301.09 4430.97,4240.33 4457.85,4213.45 v1(4494.9,4213.45) 4514.56,4193.79 R135.1@4537.25,4193.79 ; v1(5933.38,4168.95) 5933.38,4143.54 5942.89,4134.03 J11.27@6007.91,4134.03
AR_DP5: J11.29 R137.1 U2.M1 | length 2321.9
  Top Layer w6.7: U2.M1@4324.2,4219.87 4331.08,4212.98 4398.06,4212.98 4415.2,4230.12 4501.7,4230.12 4518.72,4213.1 v1(4519,4213.1)
  Sig1 w5.95: v1(4519,4213.1) 4665.01,4067.1 4735.13,4067.1 4768.85,4033.38 4768.85,4023 4854.14,3937.72 4919.45,3937.72 4930.69,3948.95 5047.08,3948.95 5063.39,3932.63 5097.55,3932.63 5109.44,3944.53 5130.71,3944.53 5151.36,3965.17 5394.76,3965.17 5467.37,4037.79 5790.28,4037.79 5815.02,4062.53 5918.43,4062.53 5924.37,4068.47 5924.37,4085.74 5917.05,4093.05 5752.9,4093.05 5748.41,4097.55 5748.41,4127.01 5756.06,4134.66 5926.35,4134.66 v1(5946.67,4114.34)
  Bottom Layer w6.7: v1(4519,4213.1) R137.1@4537.25,4213.11 ; v1(5946.67,4114.34) J11.29@6007.91,4114.34
AR_DP6: J11.31 R138.1 U2.L2 | length 2306.4
  Top Layer w5: U2.L2@4292.7,4188.37 4308.82,4204.49 4308.82,4226.24 4318.58,4235.99 4335.56,4235.99
  Top Layer w6.7: 4335.56,4235.99 4343.78,4227.77 4395.1,4227.77 4414.05,4246.72 v1(4493.52,4246.72)
  Sig2 w5.95: v1(4493.52,4246.72) 4493.52,4245.92 4509.2,4230.24 4532.49,4230.24 4547.64,4215.1 4804.22,4215.1 4873.11,4283.98 6066.82,4283.98 6110.96,4239.84 6110.96,4195.22 6072.48,4156.74 6053.82,4156.74 5972.05,4074.97 v1(5947.9,4074.97)
  Bottom Layer w6.7: v1(4493.52,4246.72) 4499.42,4240.82 4499.42,4239.84 4509.14,4230.12 4522.89,4230.12 4525.86,4233.08 R138.1@4537.25,4233.08 ; v1(5947.9,4074.97) 5947.9,4085.2 5957.35,4094.66 J11.31@6007.91,4094.66
AR_DP7: J11.33 R140.1 U2.L1 | length 2468.5
  Top Layer w6.7: U2.L1@4324.2,4188.37 4391.19,4188.37 4410.11,4207.29 4477.59,4207.29 4488.37,4196.51 4525.88,4196.51 4526.22,4196.85 4527.5,4196.85 4535.6,4204.95 4535.6,4227.14 v1(4516.02,4246.72)
  Sig2 w5.95: v1(4516.02,4246.72) 4560.49,4246.72 4567.71,4239.49 4811.79,4239.49 4868.42,4296.12 4900.64,4296.12 4903.83,4296.12 4908.62,4300.9 4908.62,4320.84 4913.4,4325.63 4919.78,4325.63 4924.56,4320.84 4924.56,4300.9 4929.35,4296.12 4935.73,4296.12 4940.51,4300.9 4940.51,4320.84 4945.3,4325.63 4951.67,4325.63 4956.46,4320.84 4956.46,4300.9 4961.24,4296.12 4967.62,4296.12 4972.41,4300.9 4972.41,4320.84 4977.19,4325.63 4983.57,4325.63 4988.35,4320.84 4988.35,4300.9 4993.14,4296.12 4999.52,4296.12 5004.3,4300.9 5004.3,4320.84 5009.08,4325.63 5015.46,4325.63 5020.25,4320.84 5020.25,4300.9 5025.03,4296.12 5031.41,4296.12 5036.19,4300.9 5036.19,4320.84 5040.98,4325.63 5047.36,4325.63 5052.14,4320.84 5052.14,4300.9 5056.92,4296.12 5063.88,4296.12 5831.7,4296.12 5852.35,4316.78 6051.34,4316.78 6122.86,4245.26 6122.86,4171.34 6067.59,4116.07 v1(6067.59,4071.83)
  Bottom Layer w5.95: J11.33@6007.91,4074.97 6064.44,4074.97 v1(6067.59,4071.83)
  Bottom Layer w6.7: v1(4516.02,4246.72) 4521.7,4252.4 R140.1@4537.25,4252.4
AR_GPIO_0: R66.1 RA5.8 U2.M2 | length 845.3
  Top Layer w6.7: v1(4276.95,4204.12) U2.M2@4292.7,4219.87
  Sig2 w5.95: v1(4276.95,4204.12) 4289.65,4191.42 4382.46,4191.42 4404.38,4213.33 4420.02,4213.33 4481.77,4275.08 4813.25,4275.08 4890.17,4352 4935.38,4352 4960.02,4376.64 v1(4960.02,4379.79)
  Bottom Layer w6.7: RA5.8@4952.34,4409.09 4952.34,4387.48 v1(4960.02,4379.79) 4962.26,4377.56 R66.1@4981.41,4377.56
AR_GPIO_1: R129.2 RA5.7 U2.L3 | length 1403.2
  Top Layer w6.7: v1(4245.46,4172.62) U2.L3@4261.2,4188.37 ; R129.2@5139.25,4519.45 5139.25,4410.27 v1(5160.84,4388.68)
  Sig2 w5.95: v1(4245.46,4172.62) 4380.49,4172.62 4409.3,4201.44 4424.95,4201.44 4486.7,4263.19 4818.67,4263.19 4893,4337.52 5109.69,4337.52 v1(5160.84,4388.68)
  Bottom Layer w6.7: RA5.7@4952.34,4424.84 4981.57,4424.84 5038,4368.41 5140.57,4368.41 v1@5158.08,4385.91
AR_GPIO_2: LD3.1 R115.1 RA5.6 U2.K3 | length 3948.2
  Top Layer w5.95: v1(6824.78,3961) R115.1@6844.78,3961
  Top Layer w6.7: v1(4245.46,4141.13) U2.K3@4261.2,4156.88 ; v1(4973.31,4455.06) 4979.31,4461.06 LD3.1@4979.31,4522.72
  Sig1 w5.95: v1(6226.68,4448.37) 6226.68,4360.49 6248.96,4338.21 6248.96,4253.51 6282.15,4220.31 6405.72,4220.31 6415.7,4210.33 6557.1,4210.33 6583.65,4236.89 6583.65,4276.96 6592.99,4286.29 6592.99,4369.07 6610.19,4386.28 6731.49,4386.28 6804.35,4313.42 6804.35,4076.19 6752.78,4024.62 6752.78,3956.54 6772.44,3936.88 6800.66,3936.88 v1(6824.78,3961)
  Sig2 w5.95: v1(4245.46,4141.13) 4243.4,4143.19 4227.54,4143.19 4212.53,4158.19 4212.53,4209.79 4223.33,4220.59 4394.81,4220.59 4406.98,4232.76 4422.62,4232.76 4476.84,4286.98 4808.33,4286.98 v1@4973.31,4451.96 ; v1(4973.31,4455.06) v1@4973.31,4451.96 ; v1(6226.68,4448.37) 6210.25,4431.94 6142.57,4431.94 6095.77,4478.74 5969.43,4478.74 5941.06,4450.38 5688.19,4450.38 5580.17,4342.36 5231.36,4342.36 5168.57,4405.15 5154.02,4405.15 5108.26,4359.39 5042.72,4359.39 4973.31,4428.79 v1@4973.31,4451.96
  Bottom Layer w6.7: RA5.6@4952.34,4440.59 4956.6,4440.59 v1@4972.18,4456.16
AR_HOSTINTR1: R3.1 R152.1 RA9.6 U2.B2 | length 2217.7
  Top Layer w6.7: U2.B2@4292.7,3904.91 v1(4308.45,3889.16)
  Sig1 w5.95: v1(4979.69,3994.63) 4979.69,3995.65 5022.55,4038.5 5078.71,4038.5 5118.81,4078.61 5228.77,4078.61 5315.76,4165.59 5315.76,4208.37 5189.21,4334.92 5189.21,4422.01 5289.86,4522.66 5497.63,4522.66 5667.88,4352.4 v1(5675.9,4352.4)
  Sig2 w5.95: v1(4308.45,3889.16) 4349.35,3889.16 4361.01,3877.5 4361.01,3850.85 4399.45,3812.41 4514.33,3812.41 4608.5,3906.58 4731.17,3906.58 4841.6,4017 4957.32,4017 v1(4979.69,3994.63)
  Bottom Layer w6.7: R3.1@4284.8,3889.16 v1(4308.45,3889.16) ; RA9.6@4960.68,3987.64 4969.78,3987.64 v1@4976.78,3994.63 ; v1(5675.9,4352.4) 5678.13,4350.18 R152.1@5678.13,4328.4
AR_LVDS_0_N: R149.1 RA6.7 U2.N1 | length 1347.9
  Top Layer w5.1: v1(4308.45,4267.11) U2.N1@4324.2,4251.36 ; v1@4955.46,4257.89 4951.31,4262.04 4951.31,4278.22 R149.1@4956.17,4283.07
  Sig1 w4.8: v1@4303.79,4271.41 4308.48,4266.72 4432.79,4266.72 4436.88,4262.64 4532.51,4262.64 4544.03,4251.11 4559.6,4251.11 4623.96,4186.74 4740.39,4186.74 4757.03,4170.1 4757.03,4122.55 4776.08,4103.49 4802.02,4103.49 4815.37,4116.84 4815.37,4160 4825.18,4169.81 4836.75,4169.81 4850.89,4155.66 4850.89,3980.23 4868.9,3962.22 4898.8,3962.22 4915.42,3978.85 4915.42,4207.44 4922.38,4214.4 4934.84,4214.4 4952.31,4231.87 4952.31,4254.74 v1@4955.46,4257.89
  Bottom Layer w5.1: RA6.7@4952.34,4292.08 4951.31,4291.06 4951.31,4262.04 v1@4955.46,4257.89
  other v1: 4954.45,4257.89
AR_LVDS_0_P: R148.1 RA6.8 U2.N2 | length 1378.2
  Top Layer w5.1: v1(4276.95,4267.11) U2.N2@4292.7,4251.36 ; R148.1@4932.76,4283.82 4937.61,4278.97 4937.61,4262.04 v1@4933.46,4257.89
  Sig1 w4.5: v1(4276.95,4267.11) 4276.95,4268.49 4291.33,4282.86 4314.97,4282.86 4315.02,4282.81 4329.69,4282.81 ; 4928.28,4230.4 4936.46,4238.59 4936.46,4254.89 v1@4933.46,4257.89
  Sig1 w4.8: 4315.11,4282.72 4443.56,4282.72 4447.64,4278.64 4539.13,4278.64 4550.66,4267.11 4566.22,4267.11 4630.59,4202.74 4747.02,4202.74 4773.03,4176.73 4773.03,4129.17 4782.71,4119.49 4795.39,4119.49 4799.37,4123.47 4799.37,4166.62 4813.87,4181.12 4818.56,4185.81 4843.37,4185.81 4866.89,4162.29 4866.89,3986.86 4875.53,3978.22 4892.17,3978.22 4899.42,3985.47 4899.42,4214.07 4915.75,4230.4 4928.28,4230.4
  Bottom Layer w5.1: v1@4933.46,4257.89 4924.29,4267.07 4924.29,4276.21 4929.55,4281.47 4933.77,4281.47 4936.59,4284.29 RA6.8@4936.59,4292.08
  other v1: 4932.45,4257.89
AR_LVDS_1_N: R147.1 RA7.5 U2.P1 | length 1514.7
  Top Layer w5.1: v1(4308.45,4298.61) U2.P1@4324.2,4282.86 ; v1@4996.38,4240.79 R147.1@5020,4240.79
  Sig1 w4.5: v1@4314.97,4298.61 4349.94,4298.61 ; v1@4315,4298.63 4461.96,4298.63
  Sig1 w4.8: 4349.94,4298.61 4462.36,4298.61 4474.02,4310.27 4585.93,4310.27 4594.45,4318.79 4713.9,4318.79 4723.1,4309.59 4723.1,4299.06 4718.12,4294.08 4625.17,4294.08 4609.92,4278.83 4609.92,4253.99 4639.23,4224.67 4762.1,4224.67 4775.28,4237.85 4775.28,4251.38 4783.96,4260.05 4801.76,4260.05 4810.09,4251.73 4810.09,4225.13 4825.25,4209.97 4864.39,4209.97 4883.45,4229.03 4883.45,4276.27 4904.75,4297.57 4989.83,4297.57 5016.62,4270.79 5016.62,4250.37 5014.7,4248.45 5008.13,4248.45 5005.1,4251.48 5005.1,4269.16 5002.59,4271.67 4996.91,4271.67 4994.13,4268.9 4994.13,4258.43 4980.76,4245.35 4980.76,4237.78 4985.99,4232.54 4992.41,4232.54 4995.28,4235.41 v1(4995.28,4239.89)
  Bottom Layer w5.1: RA7.5@4952.83,4236.76 4972.37,4236.76 4988.26,4252.65 4998.09,4252.65 5000.59,4250.16 5000.59,4245.19 v1(4995.28,4239.89)
AR_LVDS_1_P: R146.1 RA7.6 U2.P2 | length 1377.6
  Top Layer w5.1: v1(4276.95,4298.61) U2.P2@4292.7,4282.86 ; v1(4995.28,4215.89) 5001.84,4222.44 5015.35,4222.44 R146.1@5020,4217.79
  Sig1 w4.5: v1(4276.95,4298.61) 4292.7,4314.36 4314.97,4314.36 ; 4315,4314.33 4455.46,4314.33
  Sig1 w4.8: 4455.46,4314.33 4467.4,4326.27 4579.3,4326.27 4587.82,4334.79 4596.74,4334.79 4720.53,4334.79 4739.1,4316.22 4739.1,4292.43 4724.75,4278.08 4631.8,4278.08 4625.92,4272.2 4625.92,4260.61 4645.86,4240.67 4755.47,4240.67 4759.28,4244.48 4759.28,4258 4777.33,4276.05 4808.39,4276.05 4826.09,4258.35 4826.09,4231.76 4831.88,4225.97 4857.76,4225.97 4867.45,4235.66 4867.45,4282.9 4898.12,4313.57 4996.46,4313.57 5032.62,4277.41 5032.62,4236.67 5016.84,4220.89 5000.28,4220.89 v1(4995.28,4215.89)
  Bottom Layer w5.1: RA7.6@4953.34,4221.53 4953.86,4222.04 4984.13,4222.04 4990.28,4215.89 v1(4995.28,4215.89)
AR_LVDS_CLK_N: R145.1 RA7.7 U2.R2 | length 1444.6
  Top Layer w5.1: v1(4276.95,4330.1) U2.R2@4292.7,4314.36 ; v1(4988.85,4165.65) 4984.7,4169.8 4984.7,4177.53 4989.02,4181.85 5007.99,4181.85 5014.75,4175.09 5043.82,4175.09 R145.1@5047.69,4171.22
  Sig1 w4.5: v1(4276.95,4330.1) 4292.7,4345.85 4346.47,4345.85 4346.57,4345.95 4431.27,4345.95 4431.74,4346.42
  Sig1 w4.8: 4431.74,4346.42 4443.39,4358.07 4566.13,4358.07 4568.59,4360.53 4568.59,4394.28 4589.88,4415.56 4614.56,4415.56 4628.27,4401.85 4628.27,4379.9 4632.61,4375.56 4644.03,4375.56 4648.37,4379.9 4648.37,4401.85 4662.08,4415.56 4686.76,4415.56 4700.47,4401.85 4700.47,4379.9 4704.81,4375.56 4733.99,4375.56 4784.96,4324.59 4801.1,4324.59 4806.33,4329.83 4806.33,4382.57 4820.04,4396.28 4844.72,4396.28 4858.43,4382.57 4858.43,4360.8 4862.77,4356.46 5007.03,4356.46 5070.47,4293.03 5070.47,4195.36 5053.39,4178.29 4989.05,4178.29 4985.85,4175.09 4985.85,4168.65 v1(4988.85,4165.65)
  Bottom Layer w5.1: RA7.7@4953.34,4205.78 4954.37,4204.75 4970.09,4204.75 4984.7,4190.14 4984.7,4169.8 v1(4988.85,4165.65)
AR_LVDS_CLK_P: R144.1 RA7.8 U2.R1 | length 1469.1
  Top Layer w5.1: v1(4308.45,4330.1) U2.R1@4324.2,4314.36 ; v1(4966.85,4165.65) 4966.85,4179.06 4983.34,4195.55 5013.67,4195.55 5020.43,4188.79 5044.92,4188.79 R144.1@5048.79,4192.66
  Sig1 w4.8: v1(4308.45,4330.1) 4438.05,4330.1 4450.02,4342.07 4572.76,4342.07 4584.59,4353.9 4584.59,4387.65 4596.51,4399.56 4607.93,4399.56 4612.27,4395.23 4612.27,4373.28 4625.98,4359.56 4650.66,4359.56 4664.37,4373.28 4664.37,4395.23 4668.71,4399.56 4680.13,4399.56 4684.47,4395.23 4684.47,4373.28 4698.18,4359.56 4727.36,4359.56 4778.34,4308.59 4807.72,4308.59 4822.33,4323.2 4822.33,4343.44 4822.33,4354.17 4822.33,4375.94 4826.67,4380.28 4838.09,4380.28 4842.43,4375.94 4842.43,4354.17 4856.14,4340.46 5000.41,4340.46 5054.47,4286.4 5054.47,4201.99 5046.76,4194.29 4950.32,4194.29 4942.74,4186.71 4942.74,4170.03 4947.13,4165.65 v1(4966.85,4165.65)
  Bottom Layer w5.1: RA7.8@4954.37,4191.05 RA7.8@4953.34,4190.03 4961.5,4190.03 4964.41,4187.12 4964.41,4180.64 4961.93,4178.16 4945.93,4178.16 4940.41,4172.64 4940.41,4168.9 4943.66,4165.65 v1(4966.85,4165.65)
AR_LVDS_FRCLK_N: R143.1 RA8.5 U2.T2 | length 1399.8
  Top Layer w5.1: U2.T2@4292.7,4345.85 v1(4308.45,4361.6) ; v1(4966.85,4136.73) 4973.39,4130.19 4973.39,4117.17 R143.1@4967.77,4111.55
  Sig1 w4.5: 4324.2,4377.35 4351.72,4377.35
  Sig1 w4.8: v1(4308.45,4361.6) 4324.2,4377.35 ; 4351.72,4377.35 4369.12,4394.74 4369.12,4443.73 4409.95,4484.56 4491.96,4484.56 4518.26,4458.25 4824.18,4458.25 4848.55,4433.88 4983.07,4433.88 5109.57,4307.38 5109.57,4159.2 5038.01,4087.64 4991.11,4087.64 4971.7,4107.05 4971.7,4131.88 v1(4966.85,4136.73)
  Bottom Layer w5.1: RA8.5@4952.69,4119.49 4953.71,4118.47 4966.52,4118.47 4973,4124.95 4973,4130.58 v1(4966.85,4136.73)
AR_LVDS_FRCLK_P: R142.1 RA8.6 U2.T1 | length 1400.6
  Top Layer w5.1: U2.T1@4324.2,4345.85 v1(4339.94,4361.6) ; R142.1@4992.71,4111.55 4987.09,4117.17 4987.09,4130.97 v1(4992.85,4136.73)
  Sig1 w4.5: 4990.31,4111.06 4990.31,4118.68 4992.11,4120.47 5012.98,4120.47 5017.87,4125.35 5017.87,4133.27 5014.4,4136.73 v1(4992.85,4136.73)
  Sig1 w4.8: v1(4339.94,4361.6) 4358.6,4361.6 4385.12,4388.12 4385.12,4437.1 4416.57,4468.56 4485.33,4468.56 4511.64,4442.25 4817.55,4442.25 4841.92,4417.88 4976.45,4417.88 5038.46,4355.86 5093.66,4300.66 5093.66,4165.91 5031.38,4103.64 4997.74,4103.64 4990.31,4111.06
  Bottom Layer w5.1: RA8.6@4952.69,4103.74 4953.71,4104.77 4972.19,4104.77 4986.07,4118.64 5014.98,4118.64 5019.81,4123.47 5019.81,4132.27 5015.35,4136.73 v1(4992.85,4136.73)
AR_MCUCLKOUT: RA1.2 U2.V13 | length 912.6
  Top Layer w6.7: v1(3930.5,4424.59) U2.V13@3946.24,4408.84
  Sig2 w5.95: v1(3930.5,4424.59) 3928.19,4426.9 3928.19,4480.17 3985.52,4537.5 4468.02,4537.5 4518.57,4588.05 4655.12,4588.05 v1(4685.21,4618.14)
  Bottom Layer w6.7: RA1.2@4680.21,4600.58 4680.21,4613.14 v1(4685.21,4618.14)
AR_MISO1: R121.2 U2.D1 | length 3284.5
  Top Layer w6.7: v1(4308.45,3952.15) U2.D1@4324.2,3967.9 ; v1@6621.04,4333.23 R121.2@6639.03,4333.23
  Sig2 w4.5: v1(4308.45,3952.15) 4324.2,3936.4 4354.1,3936.4 4354.83,3937.13
  Sig2 w5.95: 4354.83,3937.13 4361.44,3937.13 4372.91,3925.66 4372.91,3855.77 4404.38,3824.3 4509.4,3824.3 4603.57,3918.47 4726.25,3918.47 4836.67,4028.89 4979.54,4028.89 4996.01,4012.42 4996.01,3972.76 5043.76,3925.01 5156.99,3925.01 5200.46,3881.53 5200.46,3729.32 5213.74,3716.04 5717.64,3716.04 5766.81,3765.21 5867.81,3765.21 5925.35,3707.67 6230.52,3707.67 6249.35,3726.5 6249.35,3783.85 6353.24,3887.74 6389.62,3887.74 6411.96,3910.08 6475.27,3910.08 6515.07,3949.88 6515.07,4102.64 6544.36,4131.93 6564.41,4131.93 6595.55,4163.07 6595.55,4311.03 6617.52,4333 v1(6618.45,4333)
AR_MOSI1: R128.2 U2.F2 | length 3442.7
  Top Layer w6.7: v1(4276.95,4015.14) U2.F2@4292.7,4030.89 ; v1(6617.81,4271) 6619.56,4269.25 6670.56,4269.25 6685.71,4254.1 R128.2@6685.71,4240.71 6685.71,4167.71 6674.74,4156.74 v1(6671.76,4156.74)
  Sig1 w4.5: 4298.2,4030.13 4298.96,4030.89 4315.78,4030.89
  Sig1 w5.5: v1(4276.95,4015.14) 4281.75,4019.94 4288.01,4019.94 4298.2,4030.13
  Sig1 w5.95: 4315.78,4030.89 4316.36,4030.32 4316.57,4030.32 ; 4316,4030.89 4316.57,4030.32 ; v1(6671.76,4156.74) 6707.37,4156.74 6713.44,4150.66 6713.44,4056.18 6695.34,4038.07 6650.14,4038.07 6645.51,4033.44 6645.51,4022.15 6658.05,4009.61 6658.05,4000.78 6645.8,3988.53 6265.17,3988.53 6230.16,3953.52 6230.16,3834.57 6224.41,3828.82 6224.41,3801.5 6161.2,3738.29 5837.07,3738.29 5802.08,3773.28 5802.08,3848.99 5726.34,3924.73 5706.97,3924.73 5659.85,3877.61 5564.53,3877.61 5407.56,3720.64 5169.06,3720.64 5140.34,3749.37 5140.34,3803.39 5082.45,3861.27 5033.83,3861.27 5017.76,3877.34 4960,3877.34 4945.78,3863.12 4647.49,3863.12 4616.86,3832.48 4590.58,3832.48 4482.26,3940.8 4447.59,3940.8 4447.59,3941.6 4366.75,4022.44 4324.45,4022.44 4316.57,4030.32
AR_MSS_LOGGER: R58.1 R61.1 R131.1 U2.E2 | length 4027.5
  Top Layer w6.7: v1(4276.95,3983.65) U2.E2@4292.7,3999.4
  Sig1 w4.5: 4230.89,3967.9 4263.85,3967.9 v1@4276.95,3981.01
  Sig1 w5.95: v1(3163.55,4173.41) 3244.94,4173.41 3265.5,4152.85 3526.01,4152.85 3694.1,3984.76 3694.1,3905.76 3784.97,3814.9 4136.48,3814.9 4202.76,3881.17 4202.76,3939.76 4230.89,3967.9 ; v1@4276.95,3981.01 v1(4276.95,3983.65)
  Sig2 w4.5: 4332.4,3967.9 4347.49,3967.9 4351.37,3964.02
  Sig2 w5.95: v1(4276.95,3983.65) 4300.25,3983.65 4316,3967.9 4332.4,3967.9 ; 4351.37,3964.02 4384.8,3930.59 4384.8,3860.7 4409.3,3836.2 4504.48,3836.2 4598.64,3930.36 4721.32,3930.36 4831.75,4040.79 5024.98,4040.79 5036.27,4029.5 ; v1(5070.29,4063.51) 5036.27,4029.5 ; v1(6361.81,3928) 6191.21,3928 6185.35,3922.14 6155.37,3922.14 6142.32,3935.19 6057.76,3935.19 5976.45,4016.5 5921.24,4016.5 5899.64,4038.09 5848.9,4038.09 5836.7,4025.89 5709.49,4025.89 5682.87,4052.51 5126.86,4052.51 5070.48,3996.13 5046.92,3996.13 5036.27,4006.77 5036.27,4029.5
  Bottom Layer w6.7: v1(3163.55,4173.41) R61.1@3163.55,4195.73 ; R131.1@6331.18,3978.41 6346.63,3978.41 6350.14,3974.9 6350.14,3942.93 6361.81,3931.25 v1(6361.81,3928)
  Bottom Layer w7: R58.1@5021.79,4046.94 5053.71,4046.94 v1(5070.29,4063.51)
AR_NERR_OUT: R21.1 RA6.5 U2.U15 | length 1993.9
  Top Layer w6.7: v1(3867.5,4361.6) U2.U15@3883.25,4377.35
  Sig2 w5.95: v1(3867.5,4361.6) 3867.5,4299.23 3887.45,4279.28 4174.81,4279.28 4221.6,4232.49 4315.95,4232.49 4357.63,4274.16 4447.2,4274.16 4471.92,4298.87 4770.04,4298.87 4946.76,4475.6 4977.21,4475.6 4995.86,4456.94 4995.86,4423.5 5012.97,4406.38 5012.97,4405.96 5047.64,4371.29 5101.75,4371.29 5152.98,4422.52 5177.86,4422.52 5202.97,4397.42 5202.97,4394.51 v1(5207.55,4389.93)
  Bottom Layer w5.95: R21.1@3859.46,4307.45 3867.5,4315.49 v1(3867.5,4361.6)
  Bottom Layer w6.7: RA6.5@4983.83,4292.08 5143.25,4292.08 5207.55,4356.38 v1(5207.55,4389.93)
AR_NERRIN: R22.1 RA6.6 U2.U14 | length 2037.8
  Top Layer w6.7: v1(3899,4361.6) U2.U14@3914.75,4377.35
  Sig2 w5.95: v1(3899,4361.6) 3882.53,4345.13 3882.53,4307.96 3898.41,4292.07 4178.83,4292.07 4226.53,4244.38 4308.8,4244.38 4351.48,4287.06 4443.29,4287.06 4466.99,4310.77 4763.99,4310.77 4942.88,4489.66 5131.64,4489.66 5216.95,4404.35 5239.74,4404.35 5256.22,4387.88 v1(5258,4387.88)
  Bottom Layer w5: RA6.6@4968.09,4292.08 4968.09,4281.08 4970.49,4278.67 4995.62,4278.67
  Bottom Layer w5.95: R22.1@3886.6,4307.94 R22.1@3886.73,4307.81
  Bottom Layer w6.7: R22.1@3886.73,4308.06 3882.45,4312.34 3882.45,4345.05 v1(3899,4361.6) ; 4995.62,4278.67 5148.79,4278.67 v1(5258,4387.88)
